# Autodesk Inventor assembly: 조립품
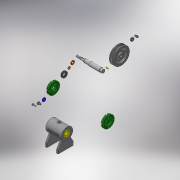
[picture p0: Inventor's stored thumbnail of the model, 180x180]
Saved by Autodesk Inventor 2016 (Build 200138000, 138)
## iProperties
Created: 2018-05
Part Number: 조립품
Material: 일반
Document SubType Name: Assembly
Designer: 201-25
Author: 201-25
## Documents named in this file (16)
- C:\Users\201-25\Desktop\480507V1001\조립품.iam
- C:\Users\201-25\Desktop\480507V1001\1-본체.ipt
- C:\Users\201-25\Desktop\480507V1001\베어링 6002.ipt
- C:\Users\201-25\Desktop\480507V1001\볼트 M4x12.ipt
- C:\Users\201-25\Desktop\480507V1001\볼트 M6x8.ipt
- C:\Users\201-25\Desktop\480507V1001\스프링와셔 8.ipt
- C:\Users\201-25\Desktop\480507V1001\앞커버.ipt
- C:\Users\201-25\Desktop\480507V1001\오일 실 15 25 7.ipt
- C:\Users\201-25\Desktop\480507V1001\와셔 6x11.5.ipt
- C:\Users\201-25\Desktop\480507V1001\와셔 8x17.ipt
- C:\Users\201-25\Desktop\480507V1001\축.ipt
- C:\Users\201-25\Desktop\480507V1001\키 3x3x12.ipt
- C:\Users\201-25\Desktop\480507V1001\V벨트풀리.ipt
- C:\Users\201-25\Desktop\480507V1001\너트 M8.ipt
- C:\Users\201-25\Desktop\480507V1001\니플 M6x0.75.ipt
- C:\Users\201-25\Desktop\480507V1001\뒤커버.ipt
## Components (2 placed, 2 different names)
1. 1-본체:1
2. V벨트풀리:1
